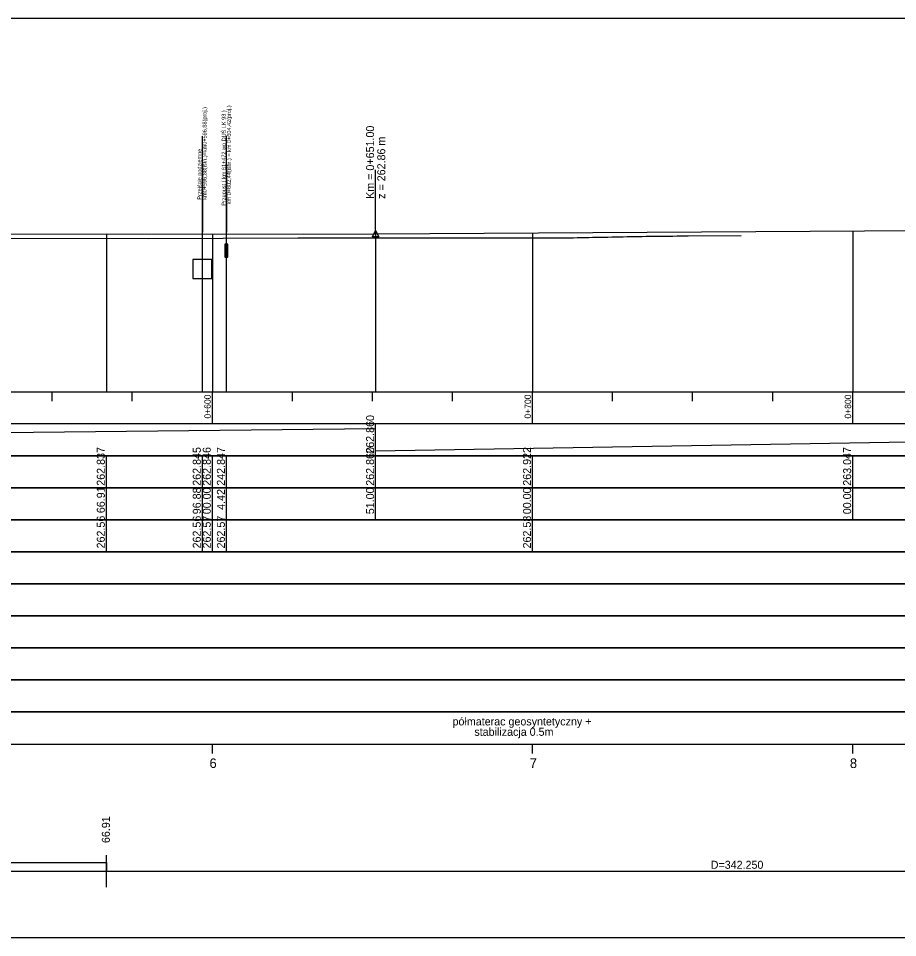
# Model space of a CAD drawing. Extents: x 6445630 to 6518227, y 5499240 to 5511716.
# Drawn here: x 6452870.6 to 6453145.2, y 5503599 to 5503886 of the extents above; entities that cross this region are included whole.
import ezdxf

# ---------------------------------------------------------------- set-up
doc = ezdxf.new("R2010")
doc.units = 0
for name, color, linetype in [('TOR_PROF-obiekty+opisy', 7, 'Continuous'), ('TOR_PROF-opisy pomocnicze', 7, 'Continuous'), ('TOR_PROF-tabelka-geometria T1', 7, 'Continuous'), ('TOR_PROF-tabelka-kilometracja', 7, 'Continuous'), ('TOR_PROF-tabelka-odleglosci T1', 7, 'Continuous'), ('TOR_PROF-tabelka-pochylenia proj T1', 7, 'Continuous'), ('TOR_PROF-tabelka-rodzaj rowu T1', 7, 'Continuous'), ('TOR_PROF-tabelka-rowyT1', 7, 'Continuous'), ('TOR_PROF-tabelka-rurociagi T1', 7, 'Continuous'), ('TOR_PROF-tabelka-rzedne istn T1', 7, 'Continuous'), ('TOR_PROF-tabelka-rzedne proj T1', 7, 'Continuous'), ('TOR_PROF-tabelka-warstwa ochronna T1', 7, 'Continuous'), ('TOR_PROF-tor istniejacy T2', 7, 'Continuous'), ('TOR_PROF-tor projektowany', 7, 'Continuous'), ('TOR_PROF-uklad odniesienia', 7, 'Continuous'), ('TOR_PROF-warstwa ochronna', 7, 'Continuous'), ('TOR_RAMKI-MASKA WYCIECIA', 7, 'Continuous')]:
    doc.layers.add(name, color=color, linetype=linetype)

msp = doc.modelspace()

# ---------------------------------------------------------------- linework, layer by layer
at = {"layer": 'TOR_PROF-obiekty+opisy'}
for p, q in [((6452928.09, 5503769.44), (6452928.09, 5503849.2)), ((6452935.63, 5503769.44), (6452935.63, 5503849.28)), ((6452928.09, 5503840.24), (6452928.09, 5503819.24)), ((6452935.63, 5503840.28), (6452935.63, 5503819.28)), ((6452935.63, 5503840.28), (6452935.63, 5503819.28)), ((6452935.63, 5503840.28), (6452935.63, 5503819.28)), ((6452935.63, 5503840.28), (6452935.63, 5503819.28)), ((6452935.63, 5503819.28), (6452935.63, 5503840.28)), ((6452931.09, 5503810.74), (6452925.09, 5503810.74)), ((6452925.09, 5503810.74), (6452925.09, 5503804.74)), ((6452931.09, 5503804.74), (6452931.09, 5503810.74)), ((6452925.09, 5503804.74), (6452931.09, 5503804.74))]:
    msp.add_line(p, q, dxfattribs=at)
for points in [[(6452936.02, 5503815.54), (6452935.1, 5503815.54), (6452935.1, 5503811.46), (6452936.02, 5503811.46)], [(6452935.94, 5503815), (6452935.19, 5503815), (6452935.19, 5503812), (6452935.94, 5503812)]]:
    msp.add_lwpolyline(points, close=True, dxfattribs=at)
for points in [[(6452936.02, 5503811.46), (6452936.02, 5503815.54), (6452935.1, 5503815.54), (6452935.1, 5503811.46), (6452936.02, 5503811.46)], [(6452935.94, 5503812), (6452935.19, 5503812), (6452935.19, 5503815), (6452935.94, 5503815), (6452935.94, 5503812)]]:
    msp.add_lwpolyline(points, dxfattribs=at)
at = {"layer": 'TOR_PROF-opisy pomocnicze'}
msp.add_line((6452982.21, 5503818.74), (6452982.21, 5503838.74), dxfattribs=at)
msp.add_lwpolyline([(6452982.21, 5503819.74), (6452983.21, 5503817.74), (6452981.21, 5503817.74)], close=True, dxfattribs=at)
at = {"layer": 'TOR_PROF-tabelka-geometria T1'}
for points in [[(6452898.12, 5503614.73), (6452898.12, 5503624.73)], [(6452331.21, 5503622.4), (6452372.81, 5503622.4), (6452372.81, 5503619.73), (6452383.33, 5503619.73), (6452383.33, 5503617.06), (6452436.45, 5503617.06), (6452436.45, 5503617.06), (6452466.45, 5503619.73), (6452466.45, 5503619.73), (6452625.6, 5503619.73), (6452625.6, 5503617.06), (6452708.86, 5503617.06), (6452708.86, 5503619.73), (6452795.82, 5503619.73), (6452795.82, 5503622.4), (6452898.12, 5503622.4), (6452898.12, 5503619.73), (6453287.5, 5503619.73), (6453287.5, 5503617.06), (6453347.77, 5503617.06), (6453347.77, 5503619.73), (6453354.03, 5503619.73), (6453354.03, 5503623.67), (6453395.6, 5503623.67)], [(6452331.21, 5503619.73), (6453431.21, 5503619.73)]]:
    msp.add_lwpolyline(points, dxfattribs=at)
at = {"layer": 'TOR_PROF-tabelka-kilometracja'}
for points in [[(6452931.21, 5503656.44), (6452931.21, 5503659.44)], [(6453031.21, 5503656.44), (6453031.21, 5503659.44)], [(6453131.21, 5503656.44), (6453131.21, 5503659.44)]]:
    msp.add_lwpolyline(points, dxfattribs=at)
at = {"layer": 'TOR_PROF-tabelka-odleglosci T1'}
msp.add_lwpolyline([(6452331.21, 5503729.44), (6453431.21, 5503729.44), (6453431.21, 5503739.44), (6452331.21, 5503739.44)], close=True, dxfattribs=at)
for points in [[(6452898.12, 5503729.44), (6452898.12, 5503739.44)], [(6452928.09, 5503729.44), (6452928.09, 5503739.44)], [(6452931.21, 5503729.44), (6452931.21, 5503739.44)], [(6452935.63, 5503729.44), (6452935.63, 5503739.44)], [(6452982.21, 5503729.44), (6452982.21, 5503739.44)], [(6453031.21, 5503729.44), (6453031.21, 5503739.44)], [(6453131.21, 5503729.44), (6453131.21, 5503739.44)]]:
    msp.add_lwpolyline(points, dxfattribs=at)
at = {"layer": 'TOR_PROF-tabelka-pochylenia proj T1'}
msp.add_lwpolyline([(6452331.21, 5503749.44), (6453431.21, 5503749.44), (6453431.21, 5503759.44), (6452331.21, 5503759.44)], close=True, dxfattribs=at)
for points in [[(6452982.21, 5503749.44), (6452982.21, 5503759.44)], [(6452331.21, 5503750.94), (6452982.21, 5503757.94)], [(6452982.21, 5503750.94), (6453395.6, 5503757.94)]]:
    msp.add_lwpolyline(points, dxfattribs=at)
at = {"layer": 'TOR_PROF-tabelka-rodzaj rowu T1'}
for points in [[(6452331.21, 5503699.44), (6453431.21, 5503699.44), (6453431.21, 5503709.44), (6452331.21, 5503709.44)], [(6452331.21, 5503679.44), (6453431.21, 5503679.44), (6453431.21, 5503689.44), (6452331.21, 5503689.44)]]:
    msp.add_lwpolyline(points, close=True, dxfattribs=at)
at = {"layer": 'TOR_PROF-tabelka-rowyT1'}
msp.add_lwpolyline([(6452331.21, 5503709.44), (6453431.21, 5503709.44), (6453431.21, 5503719.44), (6452331.21, 5503719.44)], close=True, dxfattribs=at)
at = {"layer": 'TOR_PROF-tabelka-rurociagi T1'}
msp.add_lwpolyline([(6452331.21, 5503689.44), (6453431.21, 5503689.44), (6453431.21, 5503699.44), (6452331.21, 5503699.44)], close=True, dxfattribs=at)
at = {"layer": 'TOR_PROF-tabelka-rzedne istn T1'}
msp.add_lwpolyline([(6452331.21, 5503719.44), (6453431.21, 5503719.44), (6453431.21, 5503729.44), (6452331.21, 5503729.44)], close=True, dxfattribs=at)
for points in [[(6452898.12, 5503719.44), (6452898.12, 5503729.44)], [(6452928.09, 5503719.44), (6452928.09, 5503729.44)], [(6452931.21, 5503719.44), (6452931.21, 5503729.44)], [(6452935.63, 5503719.44), (6452935.63, 5503729.44)], [(6453031.21, 5503719.44), (6453031.21, 5503729.44)]]:
    msp.add_lwpolyline(points, dxfattribs=at)
at = {"layer": 'TOR_PROF-tabelka-rzedne proj T1'}
msp.add_lwpolyline([(6452331.21, 5503739.44), (6453431.21, 5503739.44), (6453431.21, 5503749.44), (6452331.21, 5503749.44)], close=True, dxfattribs=at)
for points in [[(6452898.12, 5503739.44), (6452898.12, 5503749.44)], [(6452928.09, 5503739.44), (6452928.09, 5503749.44)], [(6452931.21, 5503739.44), (6452931.21, 5503749.44)], [(6452935.63, 5503739.44), (6452935.63, 5503749.44)], [(6452982.21, 5503739.44), (6452982.21, 5503749.44)], [(6453031.21, 5503739.44), (6453031.21, 5503749.44)], [(6453131.21, 5503739.44), (6453131.21, 5503749.44)]]:
    msp.add_lwpolyline(points, dxfattribs=at)
at = {"layer": 'TOR_PROF-tabelka-warstwa ochronna T1'}
msp.add_lwpolyline([(6452331.21, 5503669.44), (6453431.21, 5503669.44), (6453431.21, 5503679.44), (6452331.21, 5503679.44)], close=True, dxfattribs=at)
at = {"layer": 'TOR_PROF-tor istniejacy T2'}
msp.add_lwpolyline([(6453096.39, 5503818.14), (6453079.79, 5503817.99), (6453078.6, 5503817.97), (6453077.41, 5503817.96), (6453076.22, 5503817.95), (6453075.03, 5503817.94), (6453073.84, 5503817.93), (6453072.65, 5503817.91), (6453071.46, 5503817.9), (6453070.26, 5503817.88), (6453069.07, 5503817.87), (6453067.88, 5503817.85), (6453066.69, 5503817.84), (6453065.49, 5503817.82), (6453064.3, 5503817.8), (6453063.11, 5503817.78), (6453061.91, 5503817.76), (6453060.72, 5503817.74), (6453059.52, 5503817.72), (6453058.33, 5503817.7), (6453057.13, 5503817.68), (6453055.94, 5503817.66), (6453054.74, 5503817.63), (6453053.55, 5503817.61), (6453052.35, 5503817.59), (6453051.15, 5503817.56), (6453049.96, 5503817.54), (6453048.76, 5503817.51), (6453047.56, 5503817.48), (6453046.37, 5503817.46), (6453045.17, 5503817.43), (6453043.97, 5503817.4), (6453042.78, 5503817.37), (6453041.58, 5503817.34), (6453009.46, 5503817.34), (6452957.89, 5503817.39), (6452911.24, 5503817.19), (6452866.21, 5503817.29)], dxfattribs=at)
at = {"layer": 'TOR_PROF-tor projektowany'}
for p, q in [((6452982.21, 5503818.74), (6453395.6, 5503821.34)), ((6452331.21, 5503817.86), (6452982.21, 5503818.74))]:
    msp.add_line(p, q, dxfattribs=at)
for points in [[(6453131.21, 5503819.67), (6453131.21, 5503774.44), (6453131.21, 5503769.44), (6453131.21, 5503769.44)], [(6453131.21, 5503819.67), (6453131.21, 5503774.44), (6453131.21, 5503769.44), (6453131.21, 5503769.44)], [(6452898.12, 5503818.62), (6452898.12, 5503774.44), (6452898.12, 5503769.44), (6452898.12, 5503769.44)], [(6452898.12, 5503818.62), (6452898.12, 5503774.44), (6452898.12, 5503769.44), (6452898.12, 5503769.44)], [(6452931.21, 5503818.67), (6452931.21, 5503774.44), (6452931.21, 5503769.44), (6452931.21, 5503769.44)], [(6452931.21, 5503818.67), (6452931.21, 5503774.44), (6452931.21, 5503769.44), (6452931.21, 5503769.44)], [(6452982.21, 5503818.74), (6452982.21, 5503774.44), (6452982.21, 5503769.44), (6452982.21, 5503769.44)], [(6452982.21, 5503818.74), (6452982.21, 5503774.44), (6452982.21, 5503769.44), (6452982.21, 5503769.44)], [(6452982.21, 5503818.74), (6452982.21, 5503774.44), (6452982.21, 5503769.44), (6452982.21, 5503769.44)], [(6452982.21, 5503818.74), (6452982.21, 5503774.44), (6452982.21, 5503769.44), (6452982.21, 5503769.44)], [(6453031.21, 5503819.04), (6453031.21, 5503774.44), (6453031.21, 5503769.44), (6453031.21, 5503769.44)], [(6453031.21, 5503819.04), (6453031.21, 5503774.44), (6453031.21, 5503769.44), (6453031.21, 5503769.44)]]:
    msp.add_lwpolyline(points, dxfattribs=at)
at = {"layer": 'TOR_PROF-uklad odniesienia'}
for p, q in [((6452331.21, 5503769.44), (6453431.21, 5503769.44)), ((6452881.21, 5503766.44), (6452881.21, 5503769.44)), ((6452906.21, 5503766.44), (6452906.21, 5503769.44)), ((6452931.21, 5503759.44), (6452931.21, 5503769.44)), ((6452956.21, 5503766.44), (6452956.21, 5503769.44)), ((6452981.21, 5503766.44), (6452981.21, 5503769.44)), ((6453006.21, 5503766.44), (6453006.21, 5503769.44)), ((6453031.21, 5503759.44), (6453031.21, 5503769.44)), ((6453056.21, 5503766.44), (6453056.21, 5503769.44)), ((6453081.21, 5503766.44), (6453081.21, 5503769.44)), ((6453106.21, 5503766.44), (6453106.21, 5503769.44)), ((6453131.21, 5503759.44), (6453131.21, 5503769.44))]:
    msp.add_line(p, q, dxfattribs=at)
at = {"layer": 'TOR_PROF-warstwa ochronna'}
msp.add_lwpolyline([(6452331.21, 5503659.44), (6453431.21, 5503659.44), (6453431.21, 5503669.44), (6452331.21, 5503669.44)], close=True, dxfattribs=at)
at = {"layer": 'TOR_RAMKI-MASKA WYCIECIA'}
msp.add_lwpolyline([(6452266.64, 5503598.99), (6453456.64, 5503598.99), (6453456.64, 5503885.99), (6452266.64, 5503885.99)], close=True, dxfattribs=at)

# ---------------------------------------------------------------- texts
at = {"layer": 'TOR_PROF-obiekty+opisy'}
for s, p in [('  km0+596,88(istn.)=km0+596,88(proj.) ', (6452929.41, 5503828.42)), (' km 0+602,44(istn.) = km 0+604,42(proj.) ', (6452937, 5503827.5)), ('Przepust ( km 61+472 wg DUŚ LK 93 )', (6452935.38, 5503827.5)), ('  Przejście podziemne', (6452927.79, 5503828.42))]:
    msp.add_text(s, height=1.25, rotation=90, dxfattribs=at).set_placement(p)
at = {"layer": 'TOR_PROF-opisy pomocnicze'}
for s, p in [('Km = 0+651.00', (6452981.71, 5503829.64)), ('z = 262.86 m', (6452985.21, 5503829.64)), ('66.91', (6452899.2, 5503628.51))]:
    msp.add_text(s, height=2.5, rotation=90, dxfattribs=at).set_placement(p)
at = {"layer": 'TOR_PROF-tabelka-geometria T1'}
msp.add_text('D=342.250', height=2.5, dxfattribs=at).set_placement((6453086.85, 5503620.48))
at = {"layer": 'TOR_PROF-tabelka-kilometracja'}
for s, p in [('6', (6452930.32, 5503651.94)), ('7', (6453030.32, 5503651.94)), ('8', (6453130.32, 5503651.94))]:
    msp.add_text(s, height=3, dxfattribs=at).set_placement(p)
at = {"layer": 'TOR_PROF-tabelka-odleglosci T1'}
for s, p in [('66.91', (6452897.62, 5503731.51)), ('96.88', (6452927.59, 5503731.17)), ('00.00', (6452930.71, 5503731.18)), ('4.42', (6452935.13, 5503732.55)), ('51.00', (6452981.71, 5503731.18)), ('00.00', (6453030.71, 5503731.18)), ('00.00', (6453130.71, 5503731.18))]:
    msp.add_text(s, height=2.5, rotation=90, dxfattribs=at).set_placement(p)
at = {"layer": 'TOR_PROF-tabelka-pochylenia proj T1'}
msp.add_text('262.860', height=2.5, rotation=90, dxfattribs=at).set_placement((6452981.71, 5503750.07))
at = {"layer": 'TOR_PROF-tabelka-rzedne istn T1'}
for s, p in [('262.56', (6452897.62, 5503720.5)), ('262.56', (6452927.59, 5503720.5)), ('262.57', (6452930.71, 5503720.5)), ('262.57', (6452935.13, 5503720.5)), ('262.58', (6453030.71, 5503720.5))]:
    msp.add_text(s, height=2.5, rotation=90, dxfattribs=at).set_placement(p)
at = {"layer": 'TOR_PROF-tabelka-rzedne proj T1'}
for s, p in [('262.837', (6452897.62, 5503740.07)), ('262.845', (6452927.59, 5503740.07)), ('262.846', (6452930.71, 5503740.07)), ('242.847', (6452935.13, 5503740.07)), ('262.860', (6452981.71, 5503740.07)), ('262.922', (6453030.71, 5503740.08)), ('263.047', (6453130.71, 5503740.07))]:
    msp.add_text(s, height=2.5, rotation=90, dxfattribs=at).set_placement(p)
at = {"layer": 'TOR_PROF-uklad odniesienia'}
for s, p in [('0+600', (6452930.71, 5503761.04)), ('0+700', (6453030.71, 5503761.04)), ('0+800', (6453130.71, 5503761.04))]:
    msp.add_text(s, height=2, rotation=90, dxfattribs=at).set_placement(p)
at = {"layer": 'TOR_PROF-warstwa ochronna'}
for s, p in [('półmaterac geosyntetyczny + ', (6453006.22, 5503665.24)), ('stabilizacja 0.5m', (6453013.03, 5503662))]:
    msp.add_text(s, height=2.5, dxfattribs=at).set_placement(p)

doc.saveas('drawing.dxf')
